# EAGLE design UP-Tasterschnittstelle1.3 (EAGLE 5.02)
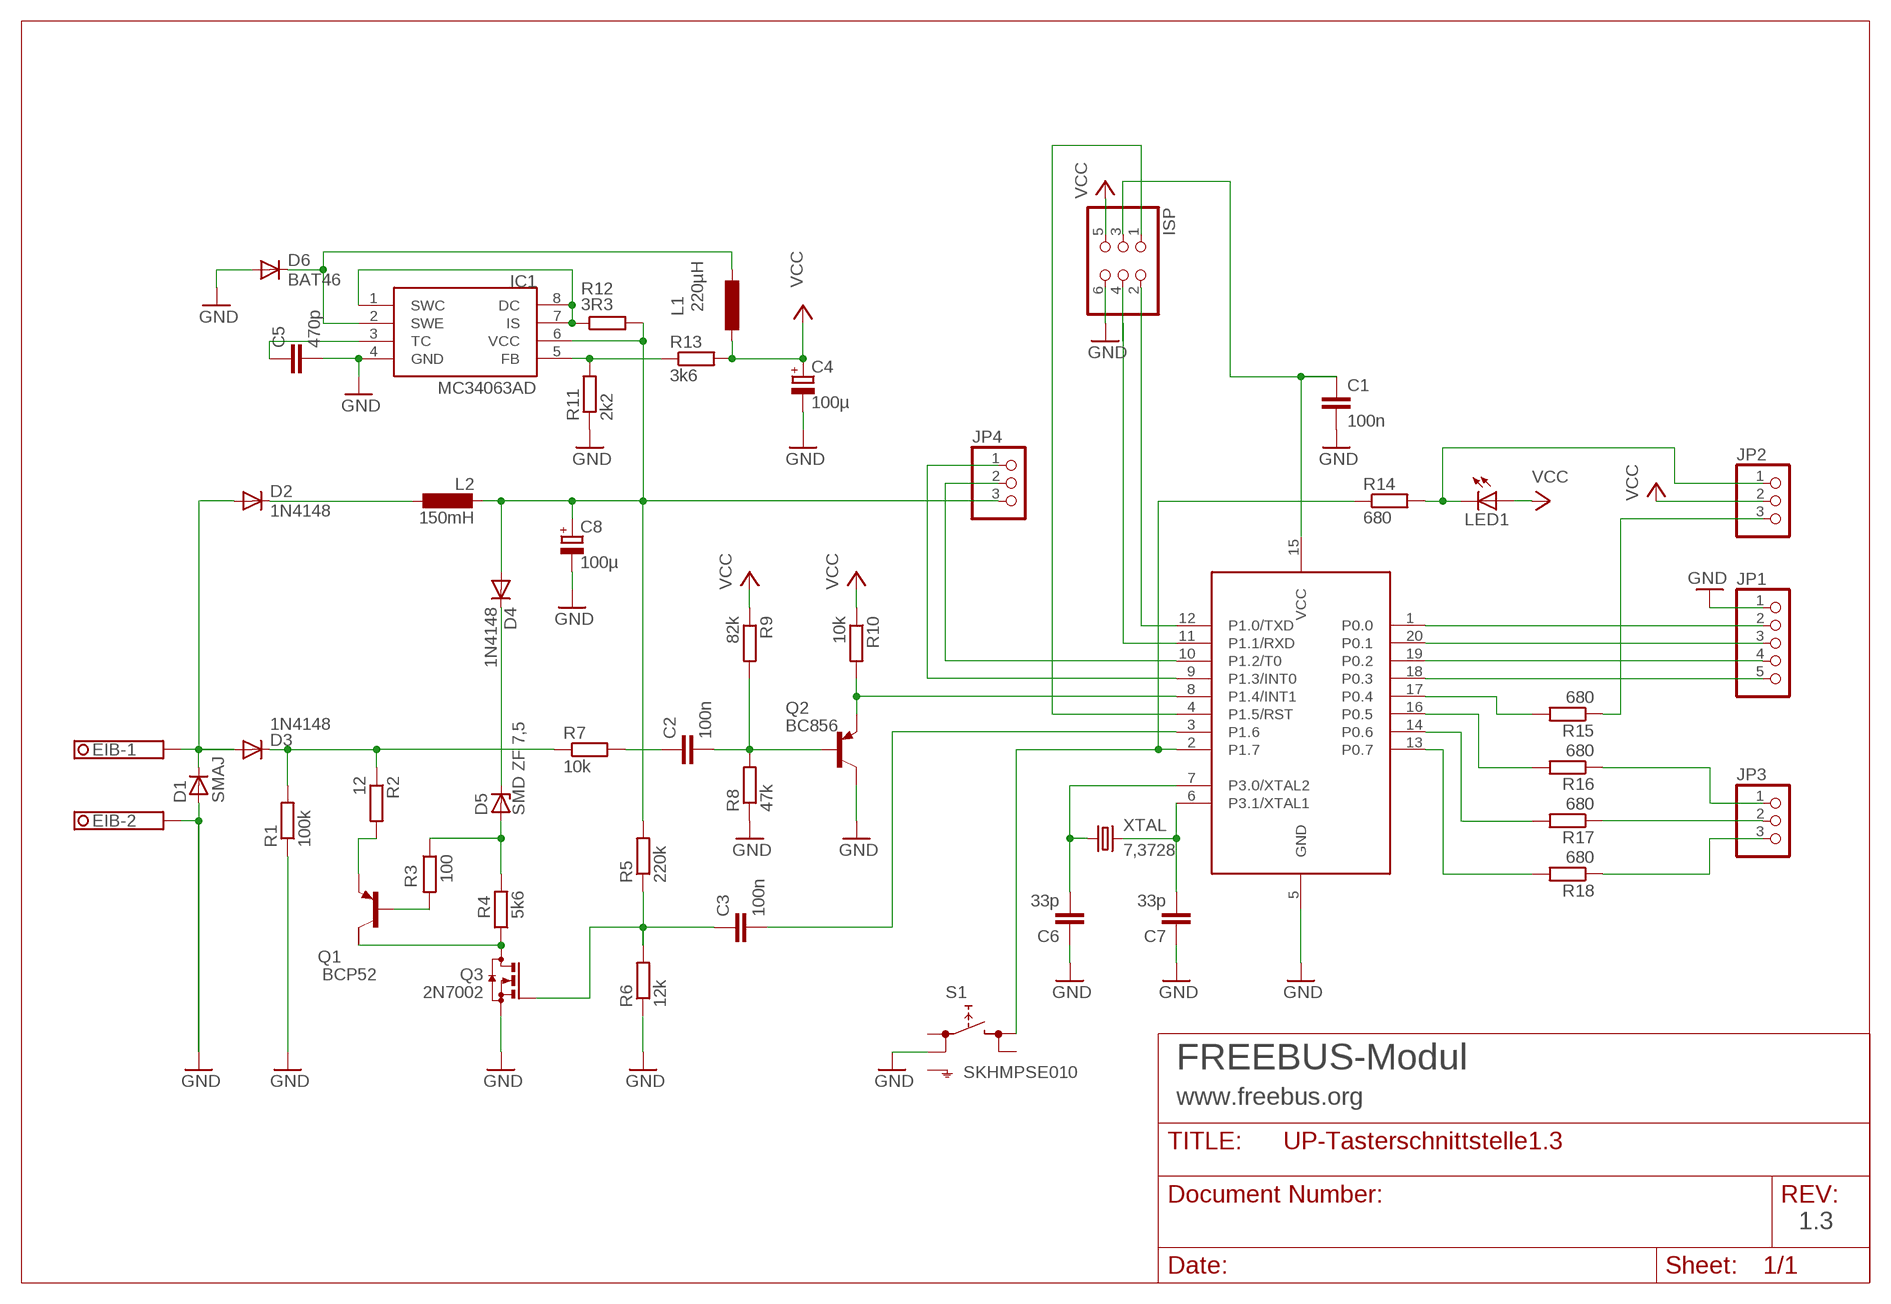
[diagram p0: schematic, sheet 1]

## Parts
C1  100n  C-EUC1206  [C1206]
C2  100n  C-EUC1206  [C1206]
C3  100n  C-EUC1206  [C1206]
C4  100µ  RCL_C_EU_H2-5X11  [2-5X11]
C5  470p  C-EUC1206  [C1206]
C6  33p  C-EUC1206  [C1206]
C7  33p  C-EUC1206  [C1206]
C8  100µ  RCL_C_EU_H3,5-8X13  [3,5-8X13]
D1  SMAJ  D-SMB  [SMB]
D2  1N4148  DIODE-MINIMELF  [MINIMELF]
D3  1N4148  DIODE-MINIMELF  [MINIMELF]
D4  1N4148  DIODE-MINIMELF  [MINIMELF]
D5  SMD ZF 7,5  ZPD  [MINIMELF]
D6  BAT46  DIODE-MINIMELF  [MINIMELF]
EIB  1751248  [1751248]
IC1  MC34063AD  [SOIC8]
IC2  LPC922FDH  [TSSOP20]
ISP  PINHD-2X3_2.00  [2X03M]
JP1  PINHD-1X5_2.00_STECKER  [1X5]
JP2  PINHD-1X3_2.00_STECKER  [1X3]
JP3  PINHD-1X3_2.00_STECKER  [1X3]
JP4  PINHD-1X3_2.00  [1X03M]
L1  220µH  L-EU2200-12.7  [2200-12.7]
L2  150mH  RCL_L-11P11PH  [RCL_11PH]
LED1  LEDCHIPLED_1206  [CHIPLED_1206]
Q1  BCP52  FZT753SMD  [SOT223]
Q2  BC856  BC856ALT1SMD  [SOT23-BEC]
Q3  2N7002  BSS123  [SOT23]
R1  100k  R-EU_M1206  [M1206]
R2  12  R-EU_R1206  [R1206]
R3  100  R-EU_R1206  [R1206]
R4  5k6  R-EU_R1206  [R1206]
R5  220k  R-EU_R1206  [R1206]
R6  12k  R-EU_R1206  [R1206]
R7  10k  R-EU_R1206  [R1206]
R8  47k  R-EU_M1206  [M1206]
R9  82k  R-EU_R1206  [R1206]
R10  10k  R-EU_R1206  [R1206]
R11  2k2  R-EU_R1206  [R1206]
R12  3R3  R-EU_M1206  [M1206]
R13  3k6  R-EU_M1206  [M1206]
R14  680  R-EU_R1206  [R1206]
R15  680  R-EU_R1206  [R1206]
R16  680  R-EU_R1206  [R1206]
R17  680  R-EU_R1206  [R1206]
R18  680  R-EU_R1206  [R1206]
S1  SKHMPSE010  [SKHMPXE010]
XTAL  7,3728  CRYSTAL_CRYSTALHC49S  [CRYSTAL_HC49/S]

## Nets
GND: C1.2 C4.- C5.2 C6.1 C7.1 C8.- D1.2(A) D6.A EIB.2 IC1.4(GND) IC2.5(GND) ISP.6 JP1.1 Q2.C Q3.2(S) R1.1 R6.1 R8.1 R11.1 S1.2(1.2)
IO1: IC2.1(P0.0) JP1.2
IO2: IC2.20(P0.1) JP1.3
IO3: IC2.19(P0.2) JP1.4
IO4: IC2.18(P0.3) JP1.5
LED1: JP2.3 R15.1
LED2: JP3.1 R16.1
LED3: JP3.2 R17.1
LED4: JP3.3 R18.1
N$5: C7.2 IC2.6(P3.1/XTAL1) XTAL.2
N$6: C6.2 IC2.7(P3.0/XTAL2) XTAL.1
N$7: C2.1 R7.2
N$8: IC2.2(P1.7) R14.1 S1.3(2.1)
N$10: IC2.9(P1.3/INT0) JP4.1
N$11: IC2.17(P0.4) R15.2
N$12: C8.+ D4.A IC1.6(VCC) JP4.3 L2.P$2 R5.2 R12.2
N$13: IC2.10(P1.2/T0) JP4.2
N$14: IC2.16(P0.5) R16.2
N$15: IC2.14(P0.6) R17.2
N$16: IC2.13(P0.7) R18.2
N$19: IC2.8(P1.4/INT1) Q2.E R10.2
N$23: C2.2 Q2.B R8.2 R9.2
N$24: C3.2 IC2.3(P1.6)
N$25: D3.C R1.2 R2.1 R7.1
N$26: IC1.5(FB) R11.2 R13.1
N$27: D6.C IC1.2(SWE) L1.2
N$28: C5.1 IC1.3(TC)
N$34: C3.1 Q3.1(G) R5.1 R6.2
N$36: D2.C L2.P$1
N$37: Q1.2(C) Q3.3(D) R4.1
N$38: D5.A R3.1 R4.2
N$39: Q1.3(E) R2.2
N$40: Q1.1(B) R3.2
N$41: D4.C D5.C
N$51: D1.1(C) D2.A D3.A EIB.1
N$61: IC1.1(SWC) IC1.7(IS) IC1.8(DC) R12.1
PROG_LED: JP2.1 LED1.C R14.2
RST: IC2.4(P1.5/RST) ISP.1
RXD: IC2.11(P1.1/RXD) ISP.4
TXD: IC2.12(P1.0/TXD) ISP.2
VCC: C4.+ ISP.5 JP2.2 L1.1 LED1.A R9.1 R10.1 R13.2
VCC_IN: C1.1 IC2.15(VCC) ISP.3
Unconnected: Q1.4(C/) S1.1(1.1) S1.4(2.2) S1.5(SH)

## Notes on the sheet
- FREEBUS-Modul
- www.freebus.org
- 1.3

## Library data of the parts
C1-C3 C5-C7 = rcl:C-EU: CAPACITOR, European symbol
C4 C8 = LPC_Gira3:RCL_C_EU_H
D1 = semicon-smd-ipc:D-: DIODE
D2-D4 D6 = diode:DIODE-: DIODE
D5 = diode:ZPD: Z DIODE
EIB = con-phoenix-350:1751248: MKDS 1/ 2-3,5 Printklemme
IC1 = mc34063:MC34063
IC2 = LPCGira:LPC922FDH
ISP = pinhead2:PINHD-2X3: PIN HEADER
JP1 = pinhead2:PINHD-1X5: PIN HEADER
JP2-JP4 = pinhead2:PINHD-1X3: PIN HEADER
L1 = rcl:L-EU: INDUCTOR, European symbol
L2 = LPC_Gira3:RCL_L-11P
LED1 = led:LED: LED
Q1 = transistor-pnp:FZT753SMD: PNP Transistor
Q2 = transistor-pnp:BC856*: PNP Transistror
Q3 = transistor-small-signal:BSS123: N-CHANNEL MOS FET
R1-R18 = rcl:R-EU_: RESISTOR, European symbol
S1 = switch:SKHMP*E010: 6.2 X 6.5mm TACT Switch (SMD) Source: http://www3.alps.co.jp/WebObjects/catalog.woa/PDF/E/Switch/Tact/SKHM/SKHM.PDF
XTAL = LPCGira:CRYSTAL_CRYSTAL: CRYSTAL

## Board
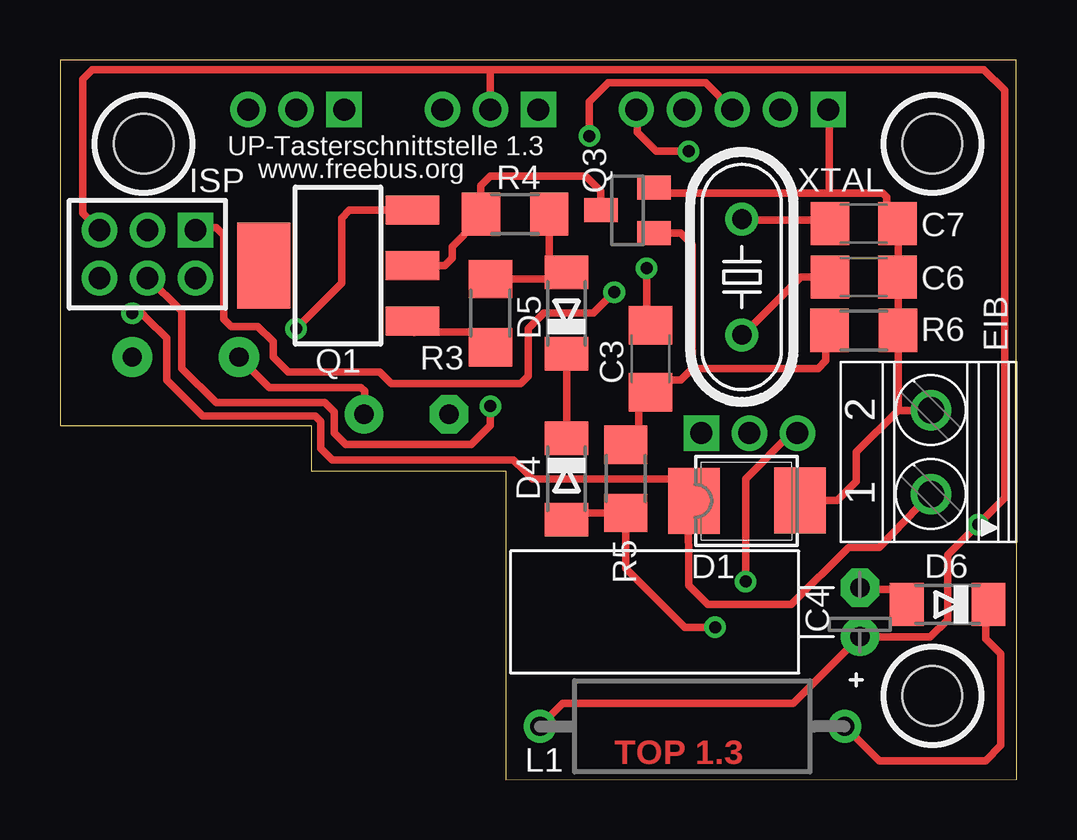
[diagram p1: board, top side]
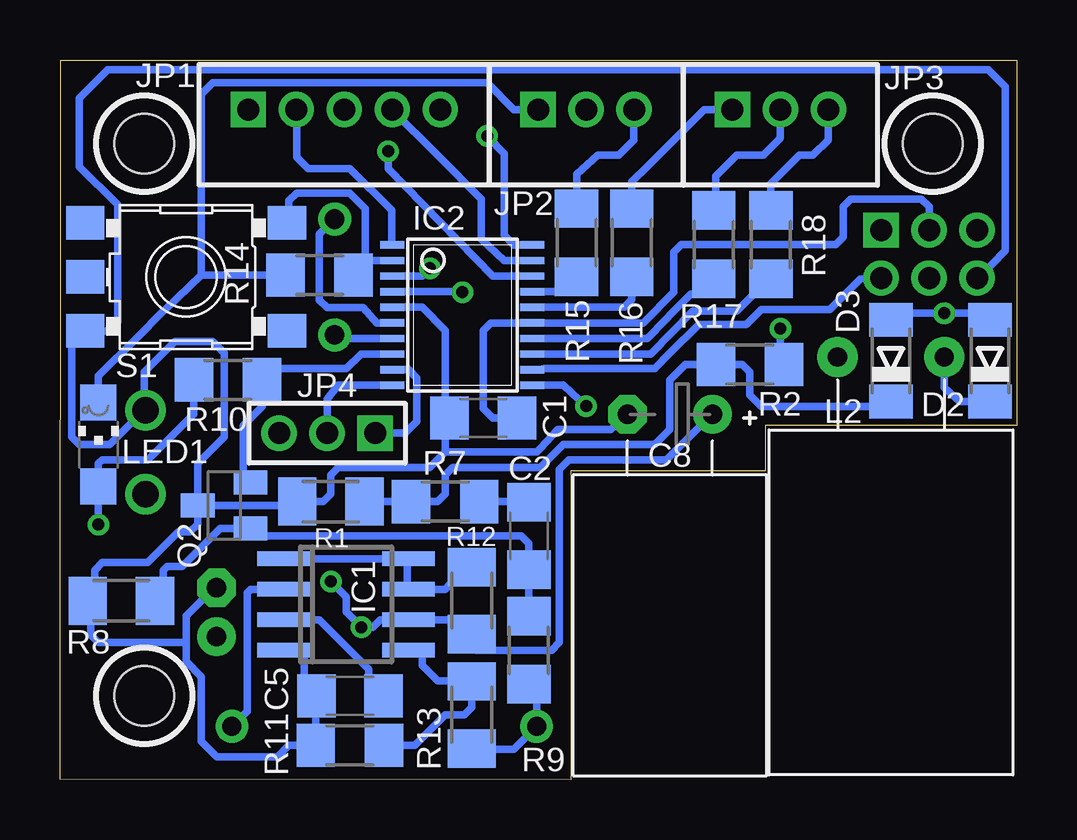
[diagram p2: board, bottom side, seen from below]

Size 39.85 x 30 mm. Coordinates in mm from the lower left corner, seen from the top.
Outline: 39.83,30 39.85,0.01 18.57,0 18.57,12.86 10.47,12.86 10.47,14.77 0,14.77 0,30 27.77,30 39.83,30
Outline: 39.84,30 39.83,30
Copper layers (1*16): Top 0.035mm / dielectric 1.5mm / Bottom 0.035mm
Design rules "ZWILLING 11mil": minimum track width 0.2mm, minimum drill 0.5mm, track to track 0.2mm, track to pad 0.2mm, pad to pad 0.2mm, via to via 0.2mm, smd to smd 0mil, copper to edge 0.2mm, drill to drill 0.2mm, minimum pad ring 11mil, minimum via ring 0.2mm, stop-mask expansion 0.1mm, vias tented up to drill 0mil, thermal gap 10mil
Holes 2.49 mm at 3.49,26.51 36.35,3.49 36.35,26.51

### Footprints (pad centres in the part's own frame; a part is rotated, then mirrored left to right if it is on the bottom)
C1206 = smd 1.6 x 1.8: 1 -1.4,0; 2 1.4,0
2-5X11 = drill 0.813 pad 1.6 round: + -1.02,0 | drill 0.813 pad 1.6 octagon: - 1.02,0
3,5-8X13 = drill 0.813 pad 1.6 round: + -1.77,-0.31 | drill 0.813 pad 1.6 octagon: - 1.77,-0.31
SMB = smd 2.159 x 2.743: 1 -2.311,-0.127; 2 2.108,-0.102
MINIMELF = smd 1.4 x 1.8: A 1.7,0; C -1.7,0
1751248 = drill 1.1 pad 1.7 round: 1 -1.75,-0.1; 2 1.75,-0.1
SOIC8 = smd 0.6 x 2.2: 1 -1.905,-2.6; 2 -0.635,-2.6; 3 0.635,-2.6; 4 1.905,-2.6; 5 1.905,2.6; 6 0.635,2.6; 7 -0.635,2.6; 8 -1.905,2.6
TSSOP20 = smd 0.305 x 0.991: 1 -2.925,-2.918; 2 -2.275,-2.918; 3 -1.625,-2.918; 4 -0.975,-2.918; 5 -0.325,-2.918; 6 0.325,-2.918; 7 0.975,-2.918; 8 1.625,-2.918; 9 2.275,-2.918; 10 2.925,-2.918; 11 2.925,2.918; 12 2.275,2.918; 13 1.625,2.918; 14 0.975,2.918; 15 0.325,2.918; 16 -0.325,2.918; 17 -0.975,2.918; 18 -1.625,2.918; 19 -2.275,2.918; 20 -2.925,2.918
2X03M = drill 0.914 square: 1 -2,-1 | drill 0.914 round: 2 -2,1; 3 0,-1; 4 0,1; 5 2,-1; 6 2,1
1X5 = drill 0.914 square: 1 -4,0 | drill 0.914 round: 2 -2,0; 3 0,0; 4 2,0; 5 4,0
1X3 = drill 0.914 square: 1 -2,0 | drill 0.914 round: 2 0,0; 3 2,0
1X03M = drill 0.914 square: 1 -2,0 | drill 0.914 round: 2 0,0; 3 2,0
2200-12.7 = drill 0.8 pad 1.27 round: 1 -6.35,0; 2 6.35,0
RCL_11PH = drill 0.8 pad 1.676 round: P$1 -2.223,0; P$2 2.223,0
CHIPLED_1206 = smd 1.5 x 1.5: A 0,-1.75; C 0,1.75
SOT223 = smd 1.219 x 2.235: 1 -2.311,-3.099; 2 0,-3.099; 3 2.311,-3.099 | smd 3.6 x 2.2: 4 0,3.099
SOT23-BEC = smd 1 x 1.4: B -0.95,-1.1; C 0,1.1; E 0.95,-1.1
SOT23 = smd 1 x 1.4: 1 -0.95,-1.1; 2 0.95,-1.1; 3 0,1.1
M1206 = smd 1.6 x 2: 1 -1.4,0; 2 1.4,0
R1206 = smd 1.6 x 1.803: 1 -1.422,0; 2 1.422,0
SKHMPXE010 = smd 1.6 x 1.4: 1 -4.2,2.25; 2 4.2,2.25; 3 -4.2,-2.25; 4 4.2,-2.25; 5 4.2,0
CRYSTAL_HC49/S = drill 0.813 round: 1 -2.413,0; 2 2.413,0

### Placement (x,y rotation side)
C1  22.22,15.08 180 bottom
C2  20.31,10.16 270 bottom
C3  24.6,17.54 90 top
C4  33.33,6.99 90 top
C5  27.78,3.49 180 bottom
C6  33.49,20.95 180 top
C7  33.49,23.18 180 top
C8  14.44,14.92 180 bottom
D1  28.73,11.75 0 top
D2  1.11,17.46 90 bottom
D3  5.23,17.46 90 bottom
D4  21.11,12.54 270 top
D5  21.11,19.45 90 top
D6  36.98,7.3 180 top
EIB  36.19,13.65 90 top
IC1  27.93,7.3 270 bottom
IC2  23.09,19.37 270 bottom
ISP  3.65,21.91 180 top
JP1  28.01,27.94 0 bottom
JP2  17.93,27.94 0 bottom
JP3  9.84,27.94 0 bottom
JP4  28.73,14.45 180 bottom
L1  26.35,2.22 0 top
L2  5.23,17.62 180 bottom
LED1  38.25,13.97 0 bottom
Q1  11.58,21.43 90 top
Q2  33.01,11.43 90 bottom
Q3  23.65,23.73 90 top
R1  28.57,11.59 0 bottom
R2  11.11,17.3 0 bottom
R3  17.93,19.45 270 top
R4  18.96,23.57 0 top
R5  23.57,12.54 270 top
R6  33.49,18.73 180 top
R7  23.81,11.59 0 bottom
R8  37.3,7.46 0 bottom
R9  20.31,5.4 90 bottom
R10  32.85,16.67 0 bottom
R11  27.78,1.43 0 bottom
R12  22.7,7.46 270 bottom
R13  22.7,2.7 270 bottom
R14  29.05,21.03 180 bottom
R15  18.33,22.38 270 bottom
R16  16.03,22.38 270 bottom
R17  12.61,22.3 270 bottom
R18  10.23,22.3 270 bottom
S1  34.6,20.96 180 bottom
XTAL  28.41,20.96 90 top

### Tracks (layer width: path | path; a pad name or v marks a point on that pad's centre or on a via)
GND
  Top 0.305: D1.2 32.38,11.65 33.17,12.44 33.17,13.65 34.92,15.4 | EIB.2 36.35,15.4 36.19,15.4 34.92,15.4 | C4.- 33.49,7.94 35.24,7.94 35.24,7.3 D6.A | 34.92,20.95 34.92,23.18 | 34.92,15.4 | 34.92,15.4 R6.1 | R6.1 | R6.1 34.92,20.8 | 33.33,24.45 34.28,24.45 34.44,24.29 34.44,23.18 34.92,23.18 | 33.33,24.45 32.06,24.45 | 32.06,24.45 30.95,24.45 27.77,24.45 24.76,24.45 Q3.2 | 34.92,23.18 C7.1 | 34.92,20.8 34.92,20.95 | 34.92,20.95 C6.1 | 34.92,20.8 | 33.33,24.45 | JP1.1 32.06,27.94 32.06,24.45
  Bottom 0.305: 39.05,28.42 37.86,29.61 32.38,29.61 3.33,29.61 1.18,29.61 0.47,28.89 0.47,22.07 1.58,20.91 ISP.6 | 30,11.59 30,11.75 30.16,11.43 Q2.C | 30,11.59 28.89,11.59 28.57,11.91 28.57,12.7 28.25,13.02 24.44,13.02 23.81,13.65 | 19.84,13.81 19.12,14.61 16.9,14.61 16.19,15.23 | 28.57,4.13 C5.2 29.2,3.65 | 34.6,5.71 34.6,6.83 33.33,8.1 C4.- | 29.2,3.65 | 29.2,3.65 29.2,1.91 R11.1 30.31,1.43 30.79,0.95 33.33,0.95 33.97,1.59 33.97,4.29 34.6,4.92 34.6,5.71 | 29.2,3.65 29.68,3.65 29.68,5.4 IC1.4 | 30,11.59 R1.1 | 16.19,15.23 16.19,15.24 | 16.19,15.23 C8.- | 39.05,28.42 | 39.05,28.42 39.05,25.56 37.46,23.97 37.46,19.37 37.46,19.05 37.78,18.7 S1.2 39.36,18.7 39.36,14.29 39.05,13.97 37.78,13.97 36.35,15.4 | 19.84,13.81 20,13.65 23.81,13.65 | 19.84,13.81 | 23.81,13.65 23.81,15.08 | IC2.5 24.76,19.69 23.81,18.73 23.81,15.08 | 23.81,15.08 23.96,15.08 C1.2 | 34.6,5.71 38.25,5.71 38.57,6.03 38.57,7.46 R8.1 38.41,7.46 38.41,8.73 38.09,9.05 36.19,9.05 34.92,10.32 34.44,10.32 34.12,10.64 Q2.C | Q2.C 34.12,13.18 33.01,14.29 33.01,17.78 33.33,18.1 33.49,18.26 35.08,18.26 36.35,16.99 36.35,15.4 | 36.35,15.4 | 36.35,15.4 EIB.2
IO1
  Bottom 0.305: IC2.1 26.03,22.29 26.03,23.73 27.77,25.48 29.52,25.48 30,25.96 | JP1.2 30,27.94 30,25.96 | 30,25.96
IO2  (via drill 0.5)
  Top 0.305: v22.06,26.83 22.06,28.26 22.85,29.05 26.9,29.05 JP1.3 | JP1.3
  Bottom 0.305: IC2.20 20.95,22.29 21.35,22.7 21.35,26.1 v22.06,26.83
IO3
  Bottom 0.305: IC2.19 21.35,21.64 22.3,22.54 22.3,24.21 24.12,26.04 26.03,27.94 JP1.4
IO4  (via drill 0.5)
  Top 0.305: v26.19,26.19 24.84,26.19 24.04,26.99 24.04,27.94 JP1.5
  Bottom 0.305: IC2.18 21.82,20.99 26.19,25.48 v26.19,26.19
LED1
  Bottom 0.305: R15.1 18.33,24.12 18.33,25.24 17.46,26.04 16.58,26.04 15.95,26.67 | JP2.3 15.95,27.94 15.95,26.67 | 15.95,26.67
LED2
  Bottom 0.305: R16.1 16.03,24.92 15.39,25.56 13.01,27.94 JP3.1 11.82,27.94
LED3
  Bottom 0.305: R17.1 12.53,23.73 12.53,25.16 11.66,26.04 10.55,26.04 9.84,26.75 JP3.2
LED4
  Bottom 0.305: R18.1 10.23,24.84 9.04,26.04 8.49,26.04 7.85,26.67 | JP3.3 7.85,27.94 7.85,26.67 | 7.85,26.67
N$5
  Top 0.305: XTAL.2 | C7.2 32.06,23.18 32.06,23.34 28.41,23.34 XTAL.2
  Bottom 0.305: IC2.6 26.66,19.04 27.22,19.68 28.73,19.68 29.04,20 29.04,20.08 29.04,21.91 29.04,22.73 XTAL.2
N$6
  Top 0.305: C6.2 30.87,20.95 28.41,18.49 | 28.41,18.49 XTAL.1 28.41,18.49
  Bottom 0.305: XTAL.1 28.41,18.41 28.41,18.38 27.77,18.39 IC2.7
N$7
  Bottom 0.305: C2.1 20.31,11.59 R7.2
N$8
  Bottom 0.305: 27.14,23.81 27.77,24.45 30,24.45 30.31,24.13 30.31,23.2 S1.3 | R14.1 | R14.1 | 27.14,21.64 27.62,21.64 R14.1 | 27.14,21.64 IC2.2 | 27.14,21.64 27.14,21.59 | 27.14,23.81 | 27.14,21.64 27.14,23.81
N$10
  Bottom 0.305: IC2.9 25.31,17.09 25,16.75 25,14.92 25.47,14.45 JP4.1
N$11
  Bottom 0.305: R15.2 18.88,20.96 18.88,20.34 IC2.17
N$12  (via drill 0.5)
  Top 0.305: v27.3,6.35 26.03,6.35 23.57,8.81 23.57,10.09 R5.2 21.03,11.12 21.03,11.08 D4.A | C8.+ 12.69,15.23 12.69,16.19 12.53,16.35 12.22,16.35 8.72,16.35 L2.P$2 | JP4.3 30.47,14.45 28.57,12.54 v28.57,8.26
  Bottom 0.305: 22.54,6.67 IC1.6 26.5,6.67 26.82,6.35 v27.3,6.35 27.93,6.99 27.93,7.62 v28.57,8.26 | 22.54,6.38 22.54,6.35 | 22.54,6.38 R12.2 | 22.54,6.67 22.54,6.38 | 22.54,6.67 22.54,5.4 19.36,5.4 19.04,5.71 19.04,12.94 18.65,13.34 14.6,13.34 12.69,15.23 | 12.69,15.23 12.69,15.24 | C8.+ 12.69,15.23
N$13
  Bottom 0.305: IC2.10 28.25,16.44 28.73,15.88 JP4.2 | JP4.2
N$14
  Bottom 0.305: R16.2 16.03,20.01 16.34,19.69 IC2.16
N$15
  Bottom 0.305: IC2.14 19.52,18.39 15.39,18.39 14.6,19.21 14.36,19.45 13.57,20.24 12.22,20.25 R17.2
N$16
  Bottom 0.254: 10.63,20.56
  Bottom 0.305: IC2.13 15.23,17.74 13.49,19.53 11.66,19.53 10.63,20.56 R18.2
N$19
  Bottom 0.305: IC2.8 27.3,17.74 27.93,17.14 28.01,17.14 29.52,17.14 29.84,17.14 31.43,17.14 | Q2.E 32.22,12.38 32.22,14.76 31.43,15.56 31.43,17.14 | 31.43,17.14 R10.2
N$23
  Bottom 0.305: 20.63,10.16 31.27,10.16 31.74,10.48 | R9.2 20.47,6.67 | 20,6.98 R9.2 | R9.2 C2.2 20.31,9.84 20.63,10.16 | R8.2 35.87,7.43 35.55,7.43 35.55,8.73 35.39,8.89 34.76,8.89 33.17,10.48 31.74,10.48 | 20.63,10.16 | 31.74,10.48 31.9,10.48 Q2.B
N$24  (via drill 0.5)
  Top 0.305: C3.2 24.44,19.34 24.44,19.82 24.44,19.92 v24.44,21.32
  Bottom 0.305: IC2.3 25.79,20.99 24.76,20.99 v24.44,21.32
N$25
  Bottom 0.305: R7.1 25.23,12.06 R7.1 | R7.1 R1.2 | R7.1 24.12,11.59 23.81,11.91 23.81,12.7 23.49,13.02 19.84,13.02 18.89,13.97 15.08,13.97 14.44,14.61 14.44,16.67 13.8,17.3 12.53,17.3 | 4.91,15.56 4.91,15.6 D3.C | 4.91,15.56 10.47,15.56 10.63,15.56 11.11,16.03 11.11,16.99 11.42,17.3 11.58,17.3 R2.1 12.53,17.3 | 4.91,15.56 | 12.53,17.3
N$26
  Bottom 0.305: R11.2 25.08,1.43 23.81,2.7 23.01,2.7 22.69,3.02 22.69,4.13 | 23.01,3.81 R13.1 22.69,4.13 | IC1.5 24.76,5.4 24.76,4.76 24.12,4.13 22.69,4.13
N$27
  Top 0.305: L1.2 34.12,0.79 38.57,0.79 39.2,1.43 39.2,5.24 38.57,5.87 38.57,7.3 D6.C
  Bottom 0.305: IC1.2 31.9,7.94 32.06,7.78 32.06,2.86 L1.2
N$28
  Bottom 0.305: IC1.3 29.04,6.67 26.98,4.6 26.98,4.13 C5.1
N$34
  Top 0.305: Q3.1 25.87,22.78 26.35,22.3 26.35,17.14 | 26.35,17.14 25.87,16.67 25.08,16.67 24.76,16.35 24.68,16.03 | R6.2 31.9,18.73 31.9,17.46 31.58,17.14 26.35,17.14 | R5.1 24.12,13.96 24.12,15.95 24.68,16.03 | 24.68,16.03 C3.1
N$36
  Bottom 0.305: D2.C 2.37,15.76 3.01,16.35 L2.P$1
N$37
  Top 0.305: Q1.2 14.76,21.11 14.76,21.19 | Q3.3 22.54,24.53 21.9,25.16 17.93,25.16 17.54,24.77 R4.1 | R4.1 17.54,23.5 | R4.1 16.82,22.7 16.34,22.23 16.34,21.75 16.03,21.43 Q1.2 | Q1.2 14.68,21.11
N$38
  Top 0.305: R3.1 20.39,20.88 20.39,21.11 | 20.39,21.11 R4.2 | 20.39,21.11 | D5.A 20.39,21.15 20.39,21.11
N$39  (via drill 0.5)
  Top 0.305: v9.84,18.8 11.74,20.71 11.74,23.42 12.06,23.74 Q1.3
  Bottom 0.305: 9.84,18.57 v9.84,18.8 | R2.2 9.84,17.46 9.84,18.57 | 9.84,18.57
N$40
  Top 0.305: Q1.1 14.76,18.64 14.76,18.65 17.85,18.65 17.85,18.02 | 17.85,18.02 | 17.85,18.02 R3.2
N$41
  Top 0.305: D4.C 21.11,14.64 21.11,15.48 21.11,15.88 21.11,16.35 21.11,16.87 D5.C
N$51  (via drill 0.5)
  Top 0.305: EIB.1 34.12,9.68 32.85,9.68 30.47,7.3 26.98,7.3 26.19,8.1 26.19,11.59 | 26.19,11.59 26.35,11.62 D1.1 | 26.19,11.59 26.03,12.54 19.68,12.54 19.36,12.86 18.88,13.34 11.34,13.34 10.87,13.81 10.87,14.92 10.63,15.16 5.95,15.16 4.44,16.67 4.44,18.41 3.64,19.21 3.41,19.45 v3.01,19.45
  Bottom 0.305: D2.A 1.1,19 1.1,19.45 v3.01,19.45 | D3.A 4.91,19 4.91,19.45 v3.01,19.45 | v3.01,19.45
N$61
  Bottom 0.305: IC1.1 IC1.8 25.39,9.21 25.39,8.26 IC1.7 23.81,7.94 22.85,9.02 | 22.85,9.02 22.54,9.05 | R12.1 22.85,9.02
PROG_LED
  Bottom 0.305: 33.97,21.04 R14.2 | 33.97,21.04 35.47,19.61 35.55,19.53 36.66,18.41 38.25,16.83 LED1.C | LED1.C | 33.97,21.04 33.97,22.54 33.97,28.57 33.49,29.05 22.06,29.05 20.95,27.94 19.92,27.94 | 19.92,27.94 JP2.1 | 19.92,27.94
RST  (via drill 0.5)
  Top 0.305: v23.09,20.32 22.93,20.16 22.22,19.45 20.15,19.45 19.52,18.81 19.52,16.83 19.2,16.51 13.8,16.51 13.33,16.99 9.52,16.99 8.88,17.62 8.88,18.26 8.25,18.89 7.14,18.89 6.82,19.21 6.82,22.7 6.5,23.02 5.71,23.02 5.71,22.91 ISP.1
  Bottom 0.305: v23.09,20.32 | IC2.4 23.09,20.34 v23.09,20.32
RXD  (via drill 0.5)
  Top 0.305: v17.93,15.57 17.93,14.76 17.14,13.97 11.9,13.97 11.42,14.45 11.42,15.32 11.03,15.72 6.5,15.72 5.07,17.14 5.07,19.53 3.64,20.95 ISP.4
  Bottom 0.305: IC2.11 18.89,16.44 17.93,15.56 v17.93,15.57
TXD
  Bottom 0.305: IC2.12 19.84,17.09 19.68,17.14 15.71,17.14 15.07,17.14 14.44,17.78 13.25,18.97 11.27,18.97 10.63,19.61 7.77,19.61 6.5,20.88 5.71,20.91 ISP.2
VCC  (via drill 0.5)
  Top 0.305: 18.01,29.61 1.34,29.61 0.95,29.21 0.95,23.62 ISP.5 | L1.1 20.95,3.17 30.55,3.17 C4.+ | C4.+ | C4.+ 36.27,5.95 36.98,6.67 36.98,9.37 v38.25,10.64 | 18.01,29.61 | 18.01,29.61 38.49,29.61 39.36,28.73 39.36,11.75 v38.25,10.64 | v38.25,10.64 | 18.01,29.61 17.93,29.53 JP2.2 | JP2.2
  Bottom 0.2: LED1.A 37.93,12.7
  Bottom 0.305: 20.79,4.13 R9.1 20,4.29 L1.1 20.95,1.27 22.54,1.27 R13.2 | LED1.A 38.25,13.18 38.09,13.34 36.19,13.34 35.47,14.05 34.28,15.24 R10.1 | R10.1 34.28,16.83 | R10.1 | LED1.A | v38.25,10.64 LED1.A
VCC_IN
  Bottom 0.305: 3.64,22.86 ISP.3 3.64,23.89 3.96,24.21 6.9,24.21 7.22,23.89 7.22,22.62 7.53,22.3 13.96,22.3 14.28,21.99 14.28,20.32 15.55,19.04 IC2.15 21.9,19.04 22.22,18.73 22.22,15.48 21.82,15.08 21.11,15.08 C1.1

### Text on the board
Top: TOP 1.3
tNames: UP-Tasterschnittstelle 1.3 | www.freebus.org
